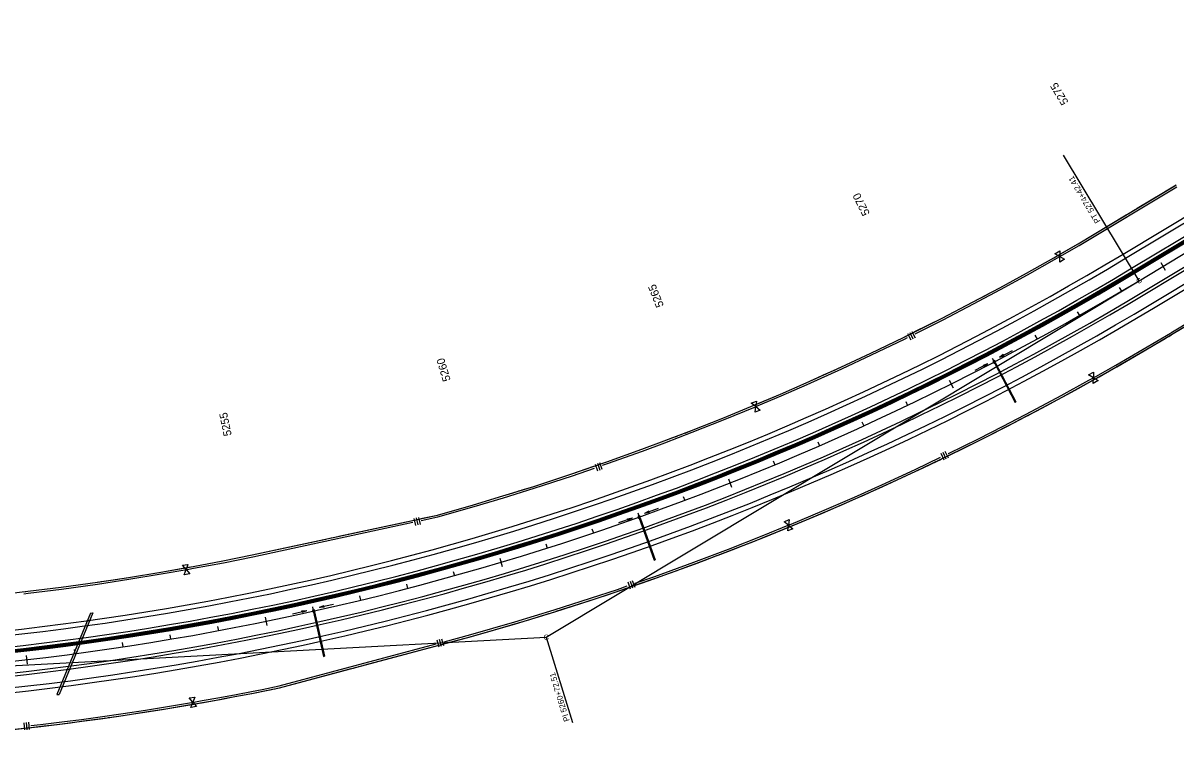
# Model space of a CAD drawing. Extents: x 192699 to 285914, y 194342 to 233219.
# Drawn here: x 269609 to 271987, y 225634 to 227117 of the extents above; entities that cross this region are included whole.
import ezdxf

# ---------------------------------------------------------------- set-up
doc = ezdxf.new("R2010")
doc.units = 0
for name, color, linetype in [('CENT LINE', 7, 'Continuous'), ('CONCRETE', 7, 'Continuous'), ('CURVE DATA', 7, 'Continuous'), ('CURVE LINE', 7, 'Continuous'), ('DRAINAGE', 7, 'Continuous'), ('DRAINAGE ARROWS', 7, 'Continuous'), ('R-W - CofA', 7, 'Continuous'), ('R_Water Annot', 7, 'Continuous'), ('ROAD', 7, 'Continuous'), ('SHOULDER', 7, 'Continuous'), ('STATIONING1', 7, 'Continuous'), ('TEXT', 7, 'Continuous'), ('WRSF', 7, 'Continuous')]:
    doc.layers.add(name, color=color, linetype=linetype)

msp = doc.modelspace()

# ---------------------------------------------------------------- linework, layer by layer
at = {"layer": 'CENT LINE'}
msp.add_line((271911, 226585.9), (279924.8, 231407.4), dxfattribs=at)
msp.add_arc((268957.2, 231495.4), 5729.6, 273.06668, 301.03334, dxfattribs=at)
at = {"layer": 'CONCRETE'}
for p, q in [((271899.7, 226604.7), (279913.5, 231426.2)), ((271901.8, 226601.3), (279915.5, 231422.8))]:
    msp.add_line(p, q, dxfattribs=at)
for radius in [5707.6, 5711.6]:
    msp.add_arc((268957.2, 231495.4), radius, 273.0667, 301.0333, dxfattribs=at)
at = {"layer": 'CURVE LINE'}
for p, q in [((270688.5, 225850.3), (271911, 226585.9)), ((269263.7, 225774), (270688.5, 225850.3))]:
    msp.add_line(p, q, dxfattribs=at)
at = {"layer": 'DRAINAGE'}
for p, q in [((271612.7, 226416.2), (271655.3, 226334.6)), ((271614.4, 226417.1), (271657.1, 226335.6)), ((271655.3, 226334.6), (271657.1, 226335.6)), ((270879.9, 226096), (270910.8, 226009.4)), ((270881.8, 226096.7), (270912.7, 226010)), ((270910.8, 226009.4), (270912.7, 226010)), ((269748.3, 225900.1), (269679, 225731.8)), ((269752.9, 225900.7), (269683.5, 225732.4)), ((269748.3, 225900.1), (269752.9, 225900.7)), ((270208.4, 225902.1), (270228.9, 225810.4)), ((270210.3, 225902.6), (270230.9, 225810.9)), ((270228.9, 225810.4), (270230.9, 225810.9)), ((269679, 225731.8), (269683.5, 225732.4))]:
    msp.add_line(p, q, dxfattribs=at)
for points in [[(271611.8, 226415.7), (271615.3, 226417.6), (271613.3, 226421.1), (271609.8, 226419.2)], [(270879, 226095.7), (270882.7, 226097.1), (270881.3, 226100.8), (270877.5, 226099.4)], [(270207.4, 225901.9), (270211.3, 225902.9), (270210.3, 225906.8), (270206.4, 225905.8)]]:
    msp.add_lwpolyline(points, close=True, dxfattribs=at)
at = {"layer": 'DRAINAGE ARROWS'}
for p, q in [((271631, 226433.3), (271622.9, 226427.4)), ((271632.4, 226430.7), (271622.9, 226427.4)), ((271631.1, 226433.1), (271624.3, 226428.1)), ((271632.3, 226430.9), (271624.3, 226428.1)), ((271631.2, 226432.9), (271625.9, 226428.9)), ((271632.2, 226431.1), (271625.9, 226428.9)), ((271631.4, 226432.7), (271627.3, 226429.7)), ((271632.1, 226431.3), (271627.3, 226429.7)), ((271631.5, 226432.4), (271628.8, 226430.5)), ((271631.9, 226431.6), (271628.8, 226430.5)), ((271631.6, 226432.2), (271630.3, 226431.3)), ((271631.8, 226431.8), (271630.3, 226431.3)), ((271632.4, 226430.7), (271631, 226433.3)), ((271590, 226411.9), (271599.5, 226415.2)), ((271591.4, 226409.2), (271590, 226411.9)), ((271590.1, 226411.7), (271598, 226414.4)), ((271590.2, 226411.4), (271596.5, 226413.6)), ((271590.3, 226411.2), (271595, 226412.8)), ((271590.4, 226411), (271593.5, 226412.1)), ((271590.6, 226410.8), (271592.1, 226411.3)), ((271590.8, 226410.3), (271592.1, 226411.3)), ((271590.9, 226410.1), (271593.5, 226412.1)), ((271591, 226409.9), (271595, 226412.8)), ((271591.1, 226409.7), (271596.5, 226413.6)), ((271591.2, 226409.4), (271598, 226414.4)), ((271591.4, 226409.2), (271599.5, 226415.2)), ((270899.8, 226110.3), (270890.9, 226105.5)), ((270900.9, 226107.5), (270890.9, 226105.5)), ((270899.9, 226110.1), (270892.5, 226106.1)), ((270900.8, 226107.7), (270892.5, 226106.1)), ((270900, 226109.8), (270894.1, 226106.6)), ((270900.7, 226107.9), (270894.1, 226106.6)), ((270900.1, 226109.6), (270895.7, 226107.2)), ((270900.6, 226108.2), (270895.7, 226107.2)), ((270900.2, 226109.3), (270897.3, 226107.8)), ((270900.5, 226108.4), (270897.3, 226107.8)), ((270900.3, 226109.1), (270898.9, 226108.3)), ((270900.4, 226108.7), (270898.9, 226108.3)), ((270900.9, 226107.5), (270899.8, 226110.3)), ((270856.2, 226094.8), (270866.1, 226096.7)), ((270857.2, 226091.9), (270856.2, 226094.8)), ((270856.3, 226094.5), (270864.6, 226096.1)), ((270856.4, 226094.3), (270862.9, 226095.5)), ((270856.5, 226094), (270861.4, 226095)), ((270856.6, 226093.8), (270859.8, 226094.4)), ((270856.6, 226093.6), (270858.2, 226093.9)), ((270856.8, 226093.1), (270858.2, 226093.9)), ((270856.9, 226092.9), (270859.8, 226094.4)), ((270857, 226092.4), (270862.9, 226095.5)), ((270857, 226092.6), (270861.4, 226095)), ((270857.1, 226092.2), (270864.6, 226096.1)), ((270857.2, 226091.9), (270866.1, 226096.7)), ((270184.5, 225904.6), (270194.6, 225905.3)), ((270184.5, 225904.3), (270192.9, 225905)), ((270185.2, 225901.6), (270184.5, 225904.6)), ((270184.6, 225904.1), (270191.3, 225904.6)), ((270184.7, 225903.8), (270189.6, 225904.2)), ((270184.7, 225903.6), (270188, 225903.8)), ((270184.8, 225903.3), (270186.4, 225903.5)), ((270184.9, 225902.6), (270188, 225903.8)), ((270184.9, 225902.9), (270186.4, 225903.5)), ((270185, 225902.1), (270191.3, 225904.6)), ((270185, 225902.4), (270189.6, 225904.2)), ((270185.1, 225901.9), (270192.9, 225905)), ((270185.2, 225901.6), (270194.6, 225905.3)), ((270229.6, 225915), (270220.2, 225911.3)), ((270230.3, 225912.1), (270220.2, 225911.3)), ((270229.7, 225914.7), (270221.8, 225911.6)), ((270230.2, 225912.3), (270221.8, 225911.6)), ((270229.7, 225914.5), (270223.5, 225912)), ((270230.2, 225912.6), (270223.5, 225912)), ((270229.8, 225914.3), (270225.1, 225912.4)), ((270230.1, 225912.8), (270225.1, 225912.4)), ((270229.8, 225914), (270226.8, 225912.8)), ((270230.1, 225913.1), (270226.8, 225912.8)), ((270229.9, 225913.8), (270228.4, 225913.2)), ((270230, 225913.3), (270228.4, 225913.2)), ((270230.3, 225912.1), (270229.6, 225915))]:
    msp.add_line(p, q, dxfattribs=at)
at = {"layer": 'R-W - CofA'}
for p, q in [((271978.1, 226474.5), (272284.5, 226658.8)), ((271737.5, 226641.6), (271747.5, 226647.4)), ((271747.5, 226635.8), (271737.5, 226641.6)), ((271747.5, 226647.4), (271747.5, 226635.8)), ((271747.6, 226624.2), (271747.5, 226635.8)), ((271747.5, 226635.8), (271757.6, 226630)), ((271757.6, 226630), (271747.6, 226624.2)), ((271433.7, 226476.9), (271440.3, 226463.7)), ((271438.1, 226479.1), (271444.7, 226465.9)), ((271442.5, 226481.3), (271449.1, 226468.1)), ((271806.9, 226391.4), (271817, 226397.1)), ((271817, 226397.1), (271816.8, 226385.5)), ((271816.8, 226385.5), (271806.9, 226391.4)), ((271816.7, 226373.9), (271816.8, 226385.5)), ((271826.8, 226379.6), (271816.7, 226373.9)), ((271816.8, 226385.5), (271826.8, 226379.6)), ((271111.1, 226333), (271121.8, 226337.5)), ((271120.4, 226326), (271111.1, 226333)), ((271119, 226314.5), (271120.4, 226326)), ((271121.8, 226337.5), (271120.4, 226326)), ((271120.4, 226326), (271129.6, 226319)), ((271129.6, 226319), (271119, 226314.5)), ((271501.9, 226229.8), (271508.3, 226216.5)), ((271506.4, 226231.9), (271512.8, 226218.6)), ((271510.8, 226234.1), (271517.2, 226220.7)), ((270789.1, 226207.5), (270793.9, 226193.5)), ((270793.8, 226209.1), (270798.6, 226195.1)), ((270798.4, 226210.7), (270803.2, 226196.7)), ((270415.6, 226095.4), (270418.7, 226081)), ((270420.4, 226096.5), (270423.5, 226082)), ((270425.2, 226097.5), (270428.3, 226083.1)), ((271178.8, 226088.4), (271189.6, 226092.8)), ((271188, 226081.3), (271178.8, 226088.4)), ((271189.6, 226092.8), (271188, 226081.3)), ((271186.4, 226069.8), (271188, 226081.3)), ((271197.1, 226074.2), (271186.4, 226069.8)), ((271188, 226081.3), (271197.1, 226074.2)), ((269938.1, 225998.6), (269949.5, 226000.6)), ((269945.6, 225989.7), (269938.1, 225998.6)), ((269941.6, 225978.8), (269945.6, 225989.7)), ((269949.5, 226000.6), (269945.6, 225989.7)), ((269945.6, 225989.7), (269953, 225980.8)), ((269953, 225980.8), (269941.6, 225978.8)), ((270856.6, 225964.3), (270861.5, 225950.3)), ((270861.3, 225965.9), (270866.1, 225951.9)), ((270865.9, 225967.5), (270870.8, 225953.5)), ((270467.7, 225845.9), (270471.5, 225831.6)), ((270472.5, 225847.1), (270476.3, 225832.9)), ((270463, 225844.6), (270466.8, 225830.3)), ((269952, 225724.9), (269963.5, 225726.9)), ((269963.5, 225726.9), (269959.5, 225716)), ((269959.5, 225716), (269952, 225724.9)), ((269955.5, 225705.1), (269959.5, 225716)), ((269966.9, 225707.1), (269955.5, 225705.1)), ((269959.5, 225716), (269966.9, 225707.1)), ((269610.7, 225673.7), (269612.3, 225659)), ((269615.6, 225674.2), (269617.2, 225659.5)), ((269620.4, 225674.8), (269622.1, 225660.1))]:
    msp.add_line(p, q, dxfattribs=at)
for points in [[(270464, 226102.1), (270538.5, 226123.5), (270599.2, 226141.7), (270662.5, 226161.5), (270741, 226187.3), (270813.2, 226212.1), (270885.3, 226238), (270931.4, 226255.1), (270987.7, 226276.7), (271052.6, 226302.4), (271118.4, 226329.4), (271171.4, 226351.9), (271224.6, 226375.2), (271296.2, 226407.5), (271357.6, 226436.1), (271425.3, 226468.8), (271504.9, 226508.7), (271567.6, 226541.2), (271623.7, 226571.2), (271678.9, 226601.5), (271735, 226633.1), (271785.2, 226662.1), (271987, 226782.9)], [(271752.6, 226638.7), (271787.2, 226658.8), (271989, 226779.5)], [(271844, 226697.3), (271987.3, 226783.5)], [(271907.5, 226735.3), (271987, 226782.9)], [(271888.6, 226724), (271893.8, 226727.1)], [(271898.1, 226729.7), (271903.2, 226732.7)], [(271750.6, 226642.1), (271785.2, 226662.1), (271884.3, 226721.4)], [(271449.3, 226476.4), (271506.7, 226505.2), (271569.5, 226537.8), (271625.5, 226567.7), (271680.8, 226598.1), (271736.9, 226629.7), (271752.6, 226638.7)], [(271609.7, 226563.7), (271623.7, 226571.2), (271678.9, 226601.5), (271735, 226633.1), (271750.6, 226642.1)], [(271600, 226558.5), (271605.3, 226561.3)], [(271447.5, 226480), (271504.9, 226508.7), (271567.6, 226541.2), (271585.9, 226551)], [(271590.3, 226553.3), (271595.6, 226556.2)], [(271976.3, 226478), (272073.5, 226536.5)], [(271978.1, 226474.5), (272075.5, 226533.1)], [(270533.9, 225851.9), (270624.8, 225878.1), (270706.1, 225902.8), (270780.7, 225926.7), (270836.4, 225945.3), (270913.8, 225972.1), (270994.1, 226001.2), (271065.7, 226028.3), (271134.8, 226055.4), (271192.5, 226078.8), (271258.3, 226106.5), (271325.6, 226135.7), (271382.3, 226161.1), (271450.8, 226192.8), (271519.4, 226225.6), (271581.4, 226256.2), (271632.7, 226282.2), (271691.9, 226313), (271752.2, 226345.3), (271809.7, 226376.9), (271865.4, 226408.4), (271921.8, 226441.1), (271978, 226474.5)], [(271125.7, 226328.3), (271173, 226348.3), (271226.2, 226371.6), (271297.9, 226403.9), (271359.3, 226432.6), (271427, 226465.3), (271433.5, 226468.5)], [(271291.3, 226405.2), (271296.2, 226407.5), (271357.6, 226436.1), (271425.3, 226468.8), (271431.7, 226472)], [(271821.9, 226388.3), (271863.4, 226411.8), (271919.8, 226444.5), (271976, 226477.8)], [(271962.7, 226465.3), (271967.9, 226468.4)], [(271972.2, 226471), (271977.3, 226474)], [(271823.8, 226384.9), (271865.4, 226408.4), (271921.8, 226441.1), (271958.4, 226462.8)], [(271124.2, 226331.9), (271171.4, 226351.9), (271224.6, 226375.2), (271266.7, 226394.1)], [(271271.2, 226396.2), (271276.7, 226398.7)], [(271281.2, 226400.7), (271286.7, 226403.2)], [(271517.6, 226229.1), (271517.7, 226229.2), (271579.6, 226259.7), (271630.9, 226285.7), (271690, 226316.5), (271750.3, 226348.8), (271807.8, 226380.4), (271821.9, 226388.3)], [(271682.1, 226307.9), (271691.9, 226313), (271752.2, 226345.3), (271809.7, 226376.9), (271823.8, 226384.9)], [(270804.5, 226205), (270814.5, 226208.4), (270886.6, 226234.3), (270932.7, 226251.4), (270989.1, 226273), (271054.1, 226298.8), (271119.9, 226325.8), (271125.7, 226328.3)], [(270974.6, 226271.6), (270987.7, 226276.7), (271052.6, 226302.4), (271118.4, 226329.4), (271124.2, 226331.9)], [(271662.6, 226297.8), (271667.9, 226300.6)], [(271672.3, 226302.9), (271677.7, 226305.6)], [(271519.3, 226225.6), (271519.4, 226225.6), (271581.4, 226256.2), (271632.7, 226282.2), (271658.1, 226295.5)], [(270803.3, 226208.7), (270813.2, 226212.1), (270885.3, 226238), (270931.4, 226255.1), (270949.3, 226262)], [(270954, 226263.8), (270959.6, 226265.9)], [(270964.3, 226267.7), (270969.9, 226269.9)], [(270638.9, 226154.1), (270662.5, 226161.5), (270741, 226187.3), (270786.5, 226202.9)], [(271193.3, 226083.5), (271256.7, 226110.1), (271324, 226139.3), (271380.7, 226164.7), (271449.1, 226196.4), (271501.6, 226221.5)], [(271362.4, 226152.2), (271382.3, 226161.1), (271450.8, 226192.8), (271503.3, 226217.9)], [(270465.1, 226098.3), (270539.6, 226119.7), (270600.4, 226138), (270663.7, 226157.8), (270742.2, 226183.5), (270787.8, 226199.2)], [(270464, 226102.1), (270538.5, 226123.5), (270599.2, 226141.7), (270613.1, 226146.1)], [(270617.9, 226147.6), (270623.6, 226149.4)], [(270628.4, 226150.9), (270634.1, 226152.7)], [(271194.8, 226079.8), (271258.3, 226106.5), (271325.6, 226135.7), (271337.7, 226141.2)], [(271342.3, 226143.2), (271347.8, 226145.7)], [(271352.3, 226147.7), (271357.8, 226150.2)], [(270082.1, 226020.1), (270463.9, 226102.3)], [(270082.9, 226016.3), (270413.3, 226087.4)], [(270260.5, 226058.5), (270412.5, 226091.2)], [(270429.8, 226095), (270463.9, 226102.3)], [(270430.6, 226091.1), (270464.8, 226098.5)], [(270872.1, 225961.8), (270912.5, 225975.8), (270992.8, 226004.9), (271064.3, 226031.9), (271133.4, 226059.1), (271190.9, 226082.5), (271193.3, 226083.5)], [(271044.9, 226020.4), (271065.7, 226028.3), (271134.8, 226055.4), (271192.5, 226078.8), (271194.8, 226079.8)], [(270082.1, 226020.1), (270234.1, 226052.8)], [(270239, 226053.9), (270244.8, 226055.2)], [(270249.7, 226056.2), (270255.6, 226057.5)], [(269256.2, 225913.6), (269323, 225917.6), (269407.5, 225923.7), (269488.4, 225930.9), (269555.8, 225937.7), (269619.5, 225945), (269688.2, 225953.6), (269762.6, 225963.9), (269826.7, 225973.6), (269893.8, 225984.6), (269960.2, 225996.3), (270021.7, 226007.9), (270082.1, 226019.9)], [(269950.6, 225994.6), (269960.2, 225996.3), (270021.7, 226007.9), (270082.1, 226019.9)], [(269951.3, 225990.7), (269961, 225992.4), (270022.5, 226004), (270082.9, 226016.1)], [(271024.3, 226012.6), (271029.9, 226014.7)], [(271034.6, 226016.5), (271040.2, 226018.6)], [(269611, 225940), (269620, 225941), (269688.7, 225949.7), (269763.1, 225960), (269827.3, 225969.7), (269894.5, 225980.7), (269951.3, 225990.7)], [(269791.5, 225968.3), (269826.7, 225973.6), (269893.8, 225984.6), (269950.6, 225994.6)], [(270873.4, 225958.1), (270913.8, 225972.1), (270994.1, 226001.2), (271019.6, 226010.8)], [(269610.6, 225943.9), (269619.5, 225945), (269688.2, 225953.6), (269762.6, 225963.9), (269764.8, 225964.2)], [(269769.7, 225965), (269775.6, 225965.9)], [(269780.6, 225966.6), (269786.5, 225967.5)], [(270532.9, 225855.7), (270623.7, 225881.8), (270704.9, 225906.6), (270779.5, 225930.5), (270835.1, 225949), (270855.3, 225956)], [(270708.9, 225903.7), (270780.7, 225926.7), (270836.4, 225945.3), (270856.6, 225952.3)], [(270533.9, 225851.9), (270624.8, 225878.1), (270683.1, 225895.8)], [(270687.9, 225897.3), (270693.6, 225899)], [(270698.4, 225900.5), (270704.1, 225902.2)], [(270138.4, 225745.9), (270533.9, 225851.9)], [(270478.2, 225841), (270532.6, 225855.6)], [(270479.2, 225837.2), (270533.9, 225851.9)], [(270137.6, 225749.7), (270137.6, 225749.7), (270461.1, 225836.4)], [(270311.9, 225792.4), (270462.1, 225832.6)], [(270138.1, 225745.8), (270138.4, 225745.9), (270285.8, 225785.4)], [(270290.6, 225786.7), (270296.4, 225788.2)], [(270301.2, 225789.5), (270307, 225791.1)], [(269271.2, 225634.2), (269303.8, 225636), (269346.9, 225638.7), (269407.4, 225643.1), (269466.6, 225647.9), (269531.7, 225653.9), (269577.3, 225658.6), (269613.5, 225662.6), (269645.9, 225666.3), (269690, 225671.7), (269730.5, 225676.9), (269768.8, 225682.1), (269816.1, 225688.9), (269862.7, 225696), (269904, 225702.6), (269937.1, 225708.1), (269979.6, 225715.5), (270015.8, 225722), (270049.4, 225728.3), (270081, 225734.3), (270103.6, 225738.8), (270138.4, 225745.8)], [(269965.2, 225717), (269978.9, 225719.4), (270015.1, 225725.9), (270048.7, 225732.1), (270080.2, 225738.2), (270102.8, 225742.7), (270137.6, 225749.7)], [(269965.9, 225713.1), (269979.6, 225715.5), (270015.8, 225722), (270049.4, 225728.3), (270081, 225734.3), (270103.6, 225738.8), (270118.7, 225741.8)], [(270123.6, 225742.8), (270129.5, 225744)], [(270134.4, 225745), (270138.4, 225745.8)], [(269625.2, 225667.9), (269645.5, 225670.2), (269689.5, 225675.6), (269730, 225680.8), (269768.2, 225686), (269815.5, 225692.8), (269862.1, 225699.9), (269903.4, 225706.5), (269936.4, 225712), (269965.2, 225717)], [(269806.6, 225687.6), (269816.1, 225688.9), (269862.7, 225696), (269904, 225702.6), (269937.1, 225708.1), (269965.9, 225713.1)], [(269625.7, 225664), (269645.9, 225666.3), (269690, 225671.7), (269730.5, 225676.9), (269768.8, 225682.1), (269779.9, 225683.7)], [(269784.8, 225684.4), (269790.8, 225685.3)], [(269795.7, 225686), (269801.7, 225686.9)]]:
    msp.add_lwpolyline(points, dxfattribs=at)
for radius, start, end in [(5859.6, 285.60939, 301.03335), (5869.6, 273.06668, 281.60941)]:
    msp.add_arc((268957.2, 231495.4), radius, start, end, dxfattribs=at)
at = {"layer": 'R_Water Annot'}
for p, q in [((271649.4, 226441.3), (271622.9, 226427.4)), ((271631, 226433.3), (271622.9, 226427.4)), ((271632.4, 226430.7), (271622.9, 226427.4)), ((271631.1, 226433.1), (271624.3, 226428.1)), ((271632.3, 226430.9), (271624.3, 226428.1)), ((271631.2, 226432.9), (271625.9, 226428.9)), ((271632.2, 226431.1), (271625.9, 226428.9)), ((271631.4, 226432.7), (271627.3, 226429.7)), ((271632.1, 226431.3), (271627.3, 226429.7)), ((271631.5, 226432.4), (271628.8, 226430.5)), ((271631.9, 226431.6), (271628.8, 226430.5)), ((271631.6, 226432.2), (271630.3, 226431.3)), ((271631.8, 226431.8), (271630.3, 226431.3)), ((271632.4, 226430.7), (271631, 226433.3)), ((271572.9, 226401.3), (271599.5, 226415.2)), ((271590, 226411.9), (271599.5, 226415.2)), ((271591.4, 226409.2), (271590, 226411.9)), ((271590.1, 226411.7), (271598, 226414.4)), ((271590.2, 226411.4), (271596.5, 226413.6)), ((271590.3, 226411.2), (271595, 226412.8)), ((271590.4, 226411), (271593.5, 226412.1)), ((271590.6, 226410.8), (271592.1, 226411.3)), ((271590.8, 226410.3), (271592.1, 226411.3)), ((271590.9, 226410.1), (271593.5, 226412.1)), ((271591, 226409.9), (271595, 226412.8)), ((271591.1, 226409.7), (271596.5, 226413.6)), ((271591.2, 226409.4), (271598, 226414.4)), ((271591.4, 226409.2), (271599.5, 226415.2)), ((270919.2, 226115.6), (270890.9, 226105.5)), ((270899.8, 226110.3), (270890.9, 226105.5)), ((270900.9, 226107.5), (270890.9, 226105.5)), ((270899.9, 226110.1), (270892.5, 226106.1)), ((270900.8, 226107.7), (270892.5, 226106.1)), ((270900, 226109.8), (270894.1, 226106.6)), ((270900.7, 226107.9), (270894.1, 226106.6)), ((270900.1, 226109.6), (270895.7, 226107.2)), ((270900.6, 226108.2), (270895.7, 226107.2)), ((270900.2, 226109.3), (270897.3, 226107.8)), ((270900.5, 226108.4), (270897.3, 226107.8)), ((270900.3, 226109.1), (270898.9, 226108.3)), ((270900.4, 226108.7), (270898.9, 226108.3)), ((270900.9, 226107.5), (270899.8, 226110.3)), ((270837.9, 226086.7), (270866.1, 226096.7)), ((270856.2, 226094.8), (270866.1, 226096.7)), ((270857.2, 226091.9), (270856.2, 226094.8)), ((270856.3, 226094.5), (270864.6, 226096.1)), ((270856.4, 226094.3), (270862.9, 226095.5)), ((270856.5, 226094), (270861.4, 226095)), ((270856.6, 226093.8), (270859.8, 226094.4)), ((270856.6, 226093.6), (270858.2, 226093.9)), ((270856.8, 226093.1), (270858.2, 226093.9)), ((270856.9, 226092.9), (270859.8, 226094.4)), ((270857, 226092.4), (270862.9, 226095.5)), ((270857, 226092.6), (270861.4, 226095)), ((270857.1, 226092.2), (270864.6, 226096.1)), ((270857.2, 226091.9), (270866.1, 226096.7)), ((270249.4, 225918.1), (270220.2, 225911.3)), ((270165.3, 225898.7), (270194.6, 225905.3)), ((270184.5, 225904.6), (270194.6, 225905.3)), ((270184.5, 225904.3), (270192.9, 225905)), ((270185.2, 225901.6), (270184.5, 225904.6)), ((270184.6, 225904.1), (270191.3, 225904.6)), ((270184.7, 225903.8), (270189.6, 225904.2)), ((270184.7, 225903.6), (270188, 225903.8)), ((270184.8, 225903.3), (270186.4, 225903.5)), ((270184.9, 225902.6), (270188, 225903.8)), ((270184.9, 225902.9), (270186.4, 225903.5)), ((270185, 225902.1), (270191.3, 225904.6)), ((270185, 225902.4), (270189.6, 225904.2)), ((270185.1, 225901.9), (270192.9, 225905)), ((270185.2, 225901.6), (270194.6, 225905.3)), ((270229.6, 225915), (270220.2, 225911.3)), ((270230.3, 225912.1), (270220.2, 225911.3)), ((270229.7, 225914.7), (270221.8, 225911.6)), ((270230.2, 225912.3), (270221.8, 225911.6)), ((270229.7, 225914.5), (270223.5, 225912)), ((270230.2, 225912.6), (270223.5, 225912)), ((270229.8, 225914.3), (270225.1, 225912.4)), ((270230.1, 225912.8), (270225.1, 225912.4)), ((270229.8, 225914), (270226.8, 225912.8)), ((270230.1, 225913.1), (270226.8, 225912.8)), ((270229.9, 225913.8), (270228.4, 225913.2)), ((270230, 225913.3), (270228.4, 225913.2)), ((270230.3, 225912.1), (270229.6, 225915))]:
    msp.add_line(p, q, dxfattribs=at)
at = {"layer": 'ROAD'}
for p, q in [((271883.2, 226632.1), (280071.4, 231558.6)), ((271895.6, 226611.6), (279909.3, 231433.1)), ((271926.5, 226560.2), (279942, 231382.7)), ((271938.9, 226539.6), (279952.6, 231361.1))]:
    msp.add_line(p, q, dxfattribs=at)
for radius, start, end in [(5675.6, 273.0667, 301.0333), (5699.6, 273.0667, 301.0333), (5759.6, 273.06668, 301.03335), (5783.6, 273.06668, 301.03335)]:
    msp.add_arc((268957.2, 231495.4), radius, start, end, dxfattribs=at)
at = {"layer": 'SHOULDER'}
for p, q in [((271878, 226640.7), (280066.3, 231567.2)), ((271898.7, 226606.4), (279912.4, 231427.9)), ((271923.4, 226565.3), (279938.9, 231387.9)), ((271944, 226531), (279957.8, 231352.5))]:
    msp.add_line(p, q, dxfattribs=at)
for radius, start, end in [(5665.6, 273.0667, 301.0333), (5705.6, 273.0667, 301.0333), (5753.6, 273.06668, 301.03335), (5793.6, 273.06668, 301.03335)]:
    msp.add_arc((268957.2, 231495.4), radius, start, end, dxfattribs=at)
at = {"layer": 'STATIONING1'}
for points in [[(271955.8, 226623.3), (271965, 226607.9)], [(271870, 226571.9), (271874.6, 226564.1)], [(271783.7, 226521.8), (271788.1, 226514)], [(271696.4, 226473.2), (271700.7, 226465.3)], [(271608.4, 226426.2), (271612.5, 226418.2)], [(271519.5, 226380.7), (271527.6, 226364.6)], [(271429.8, 226336.8), (271433.7, 226328.6)], [(271339.4, 226294.4), (271343.2, 226286.2)], [(271248.3, 226253.6), (271251.9, 226245.4)], [(271156.5, 226214.4), (271159.9, 226206.1)], [(271064, 226176.8), (271070.6, 226160.1)], [(270970.8, 226140.9), (270974, 226132.5)], [(270877.1, 226106.6), (270880.1, 226098.1)], [(270782.7, 226073.9), (270785.6, 226065.3)], [(270687.8, 226042.8), (270690.6, 226034.3)], [(270592.4, 226013.5), (270597.6, 225996.2)], [(270496.5, 225985.8), (270498.9, 225977.1)], [(270400.1, 225959.7), (270402.4, 225951)], [(270303.3, 225935.4), (270305.4, 225926.7)], [(270206, 225912.8), (270208, 225904)], [(270010.5, 225872.6), (270012.1, 225863.7)], [(270108.4, 225891.8), (270112, 225874.2)], [(269912.2, 225855), (269913.7, 225846.2)], [(269714.7, 225825.2), (269715.9, 225816.2)], [(269813.6, 225839.2), (269814.9, 225830.3)], [(269615.7, 225812.8), (269617.7, 225794.9)]]:
    msp.add_lwpolyline(points, dxfattribs=at)
at = {"layer": 'TEXT'}
for points in [[(271911, 226585.9), (271755.2, 226845)], [(270688.5, 225850.3), (270742.6, 225674)]]:
    msp.add_lwpolyline(points, dxfattribs=at)
at = {"layer": 'WRSF'}
msp.add_line((271900.7, 226603), (279914.5, 231424.5), dxfattribs=at)
msp.add_arc((268957.2, 231495.4), 5709.6, 273.0667, 301.0333, dxfattribs=at)

# ---------------------------------------------------------------- texts
at = {"layer": 'CURVE DATA'}
for rotation, p in [(31.0333, (271909.2, 226578.4)), (3.0667, (270683.4, 225844.6))]:
    msp.add_text('C', height=10.8, rotation=rotation, dxfattribs=at).set_placement(p)
at = {"layer": 'STATIONING1'}
for s, rotation, p in [('5275', 121.0333, (271766.2, 226954.4)), ('5270', 116.6094, (271356.3, 226724.8)), ('5265', 111.6094, (270931.2, 226534.5)), ('5260', 106.6094, (270491.5, 226380.7)), ('5255', 101.6094, (270039.7, 226267.1))]:
    msp.add_text(s, height=16.5, rotation=rotation, dxfattribs=at).set_placement(p)
at = {"layer": 'TEXT'}
for s, rotation, p in [('PT 5274+42.41', 121.0333, (271831.7, 226708.7)), ('PI 5260+72.51', 107.05, (270736.9, 225678.3))]:
    msp.add_text(s, height=12, rotation=rotation, dxfattribs=at).set_placement(p)

doc.saveas('drawing.dxf')
